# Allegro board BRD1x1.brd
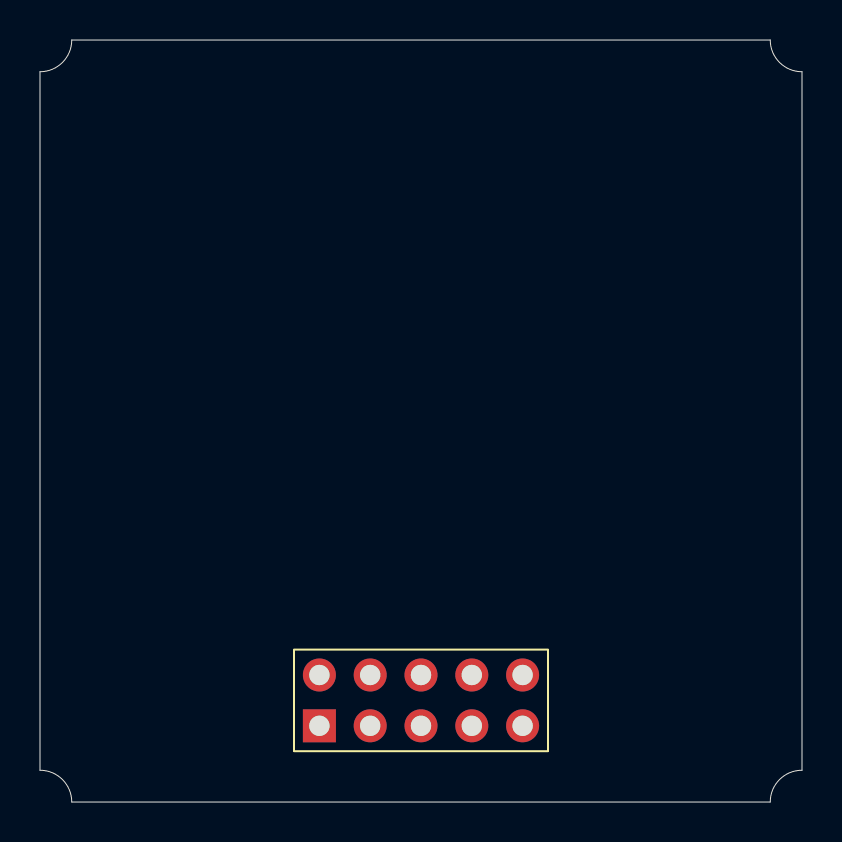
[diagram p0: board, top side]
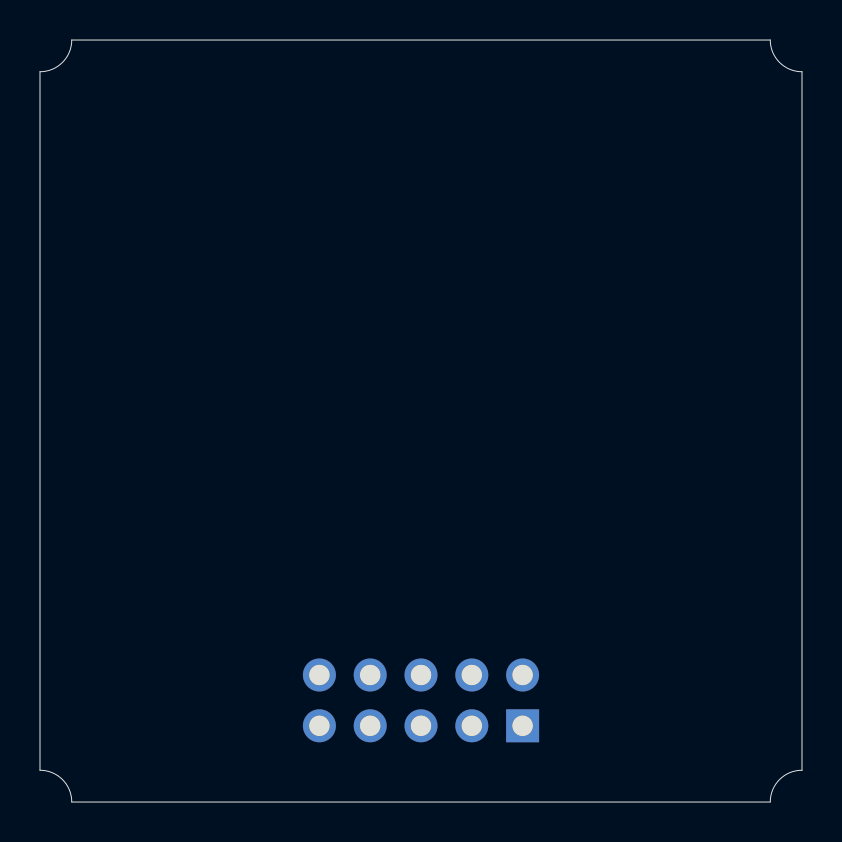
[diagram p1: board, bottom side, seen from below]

Outline 38.1 x 38.1 mm; copper layers: TOP, BOTTOM. Coordinates in mm from the lower left corner of the outline.
Outline path: 0,1.59 0,36.51 arc(1.12,36.98) 1.59,38.1 36.51,38.1 arc(36.98,36.98) 38.1,36.51 38.1,1.59 arc(36.98,1.12) 36.51,0 1.59,0 arc(1.12,1.12) 0,1.59

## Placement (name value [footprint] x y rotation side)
J1  POWER  [HDR100_10]  13.97 3.81 0 top

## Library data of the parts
J1 = CON10A

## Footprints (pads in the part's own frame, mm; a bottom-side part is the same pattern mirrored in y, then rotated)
HDR100_10
  rect 1.651x1.651 hole 1.016: 1(0,0)
  round 1.651 hole 1.016: 2(0,2.54) 3(2.54,0) 4(2.54,2.54) 5(5.08,0) 6(5.08,2.54) 7(7.62,0) 8(7.62,2.54) 9(10.16,0) 10(10.16,2.54)

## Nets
+5V: J1.5 J1.6
+15V: J1.2 J1.9
-15V: J1.1 J1.10
GND: J1.3 J1.4 J1.7 J1.8
